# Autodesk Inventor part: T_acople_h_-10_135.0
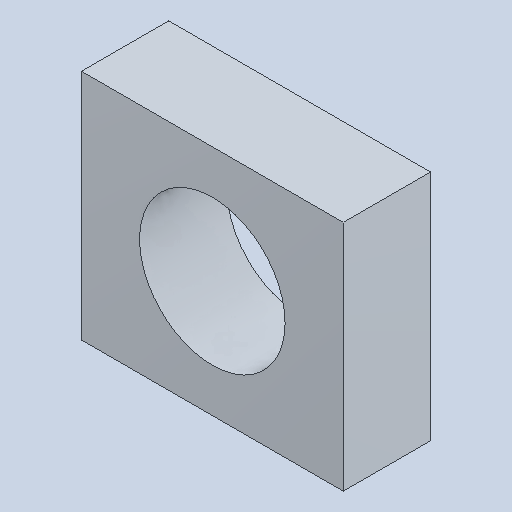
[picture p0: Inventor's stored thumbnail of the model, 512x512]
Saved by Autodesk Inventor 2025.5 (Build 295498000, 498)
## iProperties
Created: 2026-10
Part Number: T_acople_h_-10_135.0
Material: Genérico
Document SubType Name: Modeling
Designer: Luis M
Density: 1 g/cm^3
Appearance: Valor por defecto
Author: Luis M
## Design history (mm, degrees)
feature "Base1"
node "Sólido1"
